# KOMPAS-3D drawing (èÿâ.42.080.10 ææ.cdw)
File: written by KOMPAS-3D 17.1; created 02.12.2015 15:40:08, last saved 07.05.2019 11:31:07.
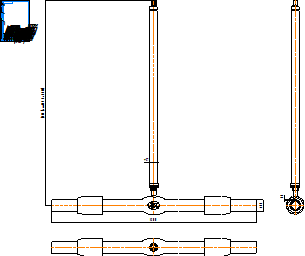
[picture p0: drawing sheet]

Sheet 1: A4, portrait

Title block, sheet 1: name: КШГ.42.080.10 СС; material: Внимание! Данный продукт является объектом авторского права ООО «Торговый Дом АДЛ». / Запрещается изменение, копирование, распространение / (в том числе путем копирования на другие сайты и ресурсы в Интернете) / или любое иное использование информации и объектов без предварительного / согласия правообладателя (ООО «Торговый Дом АДЛ»).; sheets: 1; organisation: ООО "Торговый дом АДЛ"; sheet format: A4; stored path: C:\Users\kka\KOMPAS_Work\Модели кранов для исследований\DN50\С удлинением\КШГ.32.050.40 СС ГЧ _ Шаровой кран БИВАЛ Ду50 Ру4 МПа редуцированный под приварку, с удлинением штока H=1100.cdw; drawn by: Климкович К.А.; drawn by, date: 02.12.15

Views: Вид 1, Проекционный вид 2
Referenced files in C:\Users\kka\KOMPAS_Work\Модели кранов для исследований\DN80\С удлинением\: КШТ.22.080.25 СС.a3d, КШГ.35.065.25 СС.a3d!КШГ.45.065.10 СС!Деталь (локальная).m3d
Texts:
  Klimkovich
  ADL
  (от 297 до 5000)
Dimensions and other numbers on the sheet: 1500; 57; 90; 8,2; 1:1; 1; 02.12.15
